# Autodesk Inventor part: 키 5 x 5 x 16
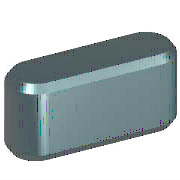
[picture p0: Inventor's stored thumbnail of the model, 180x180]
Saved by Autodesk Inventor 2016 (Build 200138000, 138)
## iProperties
IsCustomPart: 1
Created: 2012-02
Part Number: 키 5 x 5 x 16
Material: 강철, 연강
Description: 키 및 해당 키홈
Document SubType Name: Modeling
Standard: KS B 1311
Designer: mduedu
Standards Organization: KS
Language: ko-KR
Size Designation: 5 x 5 x 16
Categories: <MemberInstance><Categories><Category DisplayName="샤프트 부품" InternalName="7f7aeb1f-a693-4053-b835-cee3144e0d98" Mnemonic="SHFT"><Category DisplayName="키" Interna
Density: 1 g/cm^3
Appearance: 노란색
Author: mduedu
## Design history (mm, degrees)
workplane "Work Plane1"
workplane "Work Plane2"
sketch "스케치1"
  geometry: L1 (2.5, 2.5)-(13.5, 2.5); L2 (13.5, -2.5)-(2.5, -2.5); L3 (0, 9.4)-(0, -7.4) reference; L4 (-5, 0)-(30, 0) reference; L5 (16, 0)-(16, 7); A1 r 2.5 centre (2.5, 0) between (2.5, 2.5) and (2.5, -2.5); A2 r 2.5 centre (13.5, 0) between (13.5, -2.5) and (13.5, 2.5)
  constraints: 6 end point, 5 point on circle, 4 tangent, 3 point on line, 2 centre point, 1 horizontal, 1 parallel, 1 perpendicular
  dimensions: "d0" = 2.5 radius of A1 (= 0.5 x PB); "d13" = 2.5 radius of A2 (= 0.5 x PB); "d14" = 16 distance between parallel lines of L5 L3 (= NLG)
extrude "본체1" new body sketch "스케치1" taper "d3" = 0 deg; stored distance "d4" = 10
workplane "Work Plane3"
body "Solid1"
chamfer "모따기1" distance "d8" = 0.4 (= PHH); stored, may be unused: second distance "d9" = 0.4 (= PHH), angle "d15" = 45 deg
other parameters: "d1" = -3 (= -PNT), "d2" = 2 (= PH - PNT), "NLG" = 16 [user parameter; used in 3 equation terms], "PB" = 5 [user parameter; used in 2 equation terms], "PNT" = 3 [user parameter; used in 2 equation terms], "PH" = 5 [user parameter; used in 1 equation term], "PHH" = 0.4 [user parameter; used in 2 equation terms], "d10" = 0, "d16" = 0, "d17" = 0, "d18" = 0, "WDMIN" = 12 [user parameter], "PLB2" = 16 (= NLG) [user parameter], "WDMAX" = 17 [user parameter], "PLB1" = 16 (= NLG) [user parameter], "RR" = 0.16 [user parameter], "PUEB" = 2.3 [user parameter]
